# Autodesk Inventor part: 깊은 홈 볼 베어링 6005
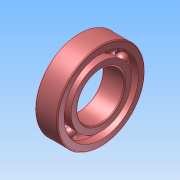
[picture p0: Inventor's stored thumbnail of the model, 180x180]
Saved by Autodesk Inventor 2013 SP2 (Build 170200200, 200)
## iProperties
Created: 2025-08
Part Number: 깊은 홈 볼 베어링 6005
Material: Generic
Document SubType Name: Modeling
Designer: i
Density: 1 g/cm^3
Author: i
변환 표준: STEP AP214IS
전처리기: Build: 200, Release: 2013 SP2 Update 6 - Date: Thu 07/17/2014
전송 단위: 밀리미터
불확실성: 0.01
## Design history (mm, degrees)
node "깊은 홈 볼 베어링 60051"
body "Solid1"
node "Solid1_1"
node "Solid1_2"
node "Solid1_3"
node "Solid1_4"
node "Solid1_5"
node "Solid1_6"
node "Solid1_7"
node "Solid1_8"
node "Solid1_9"
node "Solid1_10"
node "Solid1_11"
node "기준1"
node "기준2"
node "기준3"
node "기준4"
node "기준5"
node "기준6"
node "기준7"
node "기준8"
node "기준9"
node "기준10"
node "기준11"
node "기준12"
